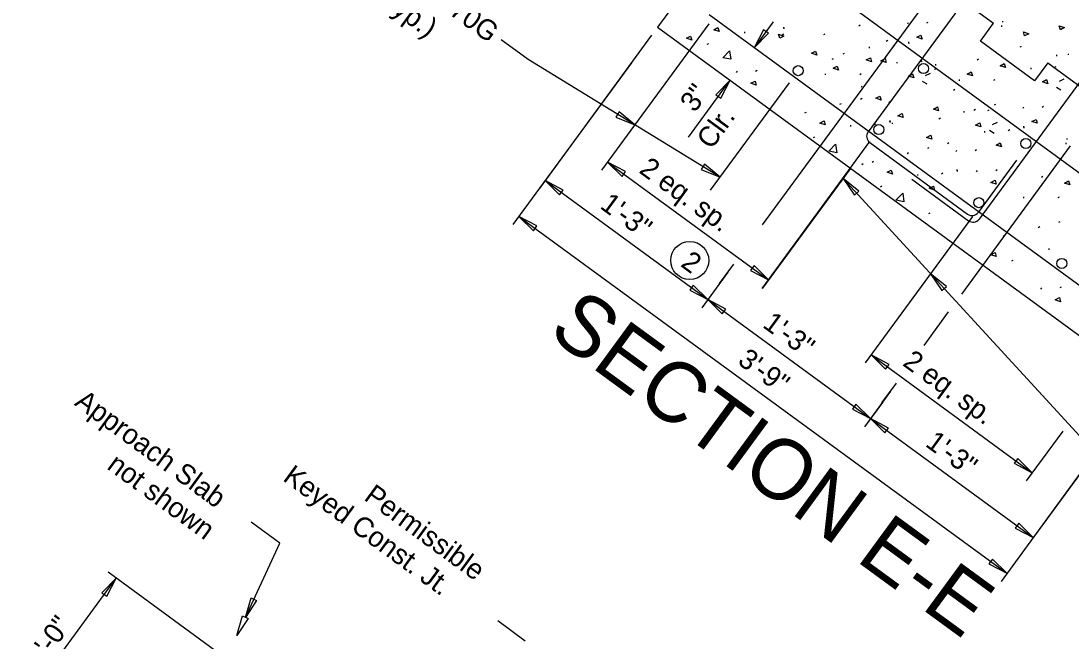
# Model space of a CAD drawing. Extents: x 1970654 to 1970899, y 796145 to 796378.
# Drawn here: x 1970798.44 to 1970824.47, y 796220.79 to 796236.18 of the extents above; entities that cross this region are included whole.
import ezdxf

# ---------------------------------------------------------------- set-up
doc = ezdxf.new("R2010")
doc.units = 0
for name, color, linetype in [('BR_AUTO DIMENSION', 7, 'Continuous'), ('BR_CONCRETE', 7, 'Continuous'), ('BR_DETAILS', 7, 'Continuous'), ('BR_REBAR', 7, 'Continuous'), ('BR_TEXT', 7, 'Continuous')]:
    doc.layers.add(name, color=color, linetype=linetype)

msp = doc.modelspace()

# ---------------------------------------------------------------- linework, layer by layer
at = {"layer": 'BR_AUTO DIMENSION'}
for p, q in [((1970816.823, 796231.114), (1970820.99, 796236.805)), ((1970817.087, 796236.158), (1970816.614, 796235.513)), ((1970815.495, 796236.106), (1970812.833, 796232.471)), ((1970811.013, 796235.217), (1970810.343, 796235.707)), ((1970814.074, 796235.823), (1970811.284, 796232.012)), ((1970813.572, 796235.138), (1970810.634, 796231.125)), ((1970815.772, 796232.296), (1970811.013, 796235.217)), ((1970814.986, 796233.289), (1970816.024, 796234.706)), ((1970815.536, 796231.973), (1970817.491, 796234.645)), ((1970816.815, 796229.532), (1970819.488, 796233.183)), ((1970821.764, 796229.399), (1970824.457, 796233.077)), ((1970812.98, 796232.672), (1970816.974, 796229.749)), ((1970818.993, 796232.507), (1970816.826, 796229.547)), ((1970818.822, 796232.27), (1970826.545, 796223.839)), ((1970811.431, 796232.214), (1970815.466, 796229.26)), ((1970810.782, 796231.327), (1970822.884, 796222.466)), ((1970822.029, 796231.322), (1970819.367, 796227.687)), ((1970815.759, 796229.661), (1970816.109, 796230.139)), ((1970815.961, 796229.938), (1970815.318, 796229.059)), ((1970815.961, 796229.938), (1970815.318, 796229.059)), ((1970815.466, 796229.26), (1970819.5, 796226.307)), ((1970820.828, 796228.121), (1970821.437, 796228.953)), ((1970819.515, 796227.888), (1970823.512, 796224.962)), ((1970819.783, 796226.694), (1970820.143, 796227.186)), ((1970819.996, 796226.984), (1970819.352, 796226.105)), ((1970819.795, 796226.709), (1970819.352, 796226.105)), ((1970819.5, 796226.307), (1970823.534, 796223.353)), ((1970824.27, 796225.997), (1970823.364, 796224.76)), ((1970824.888, 796225.202), (1970823.386, 796223.151)), ((1970824.86, 796225.163), (1970822.737, 796222.264)), ((1970804.851, 796223.217), (1970804.14, 796223.738)), ((1970804.001, 796221.371), (1970804.851, 796223.217)), ((1970798.436, 796219.117), (1970800.799, 796222.345)), ((1970806.849, 796217.915), (1970800.598, 796222.492)), ((1970810.941, 796220.785), (1970810.259, 796221.285))]:
    msp.add_line(p, q, dxfattribs=at)
for points in [[(1970816.849, 796235.961), (1970816.614, 796235.513), (1970816.97, 796235.872)], [(1970815.789, 796234.258), (1970816.024, 796234.706), (1970815.668, 796234.347)], [(1970813.189, 796233.793), (1970813.655, 796233.595), (1970813.268, 796233.921)], [(1970813.428, 796232.437), (1970812.98, 796232.672), (1970813.339, 796232.316)], [(1970815.305, 796232.494), (1970815.771, 796232.296), (1970815.384, 796232.622)], [(1970819.215, 796231.952), (1970818.822, 796232.27), (1970819.104, 796231.85)], [(1970811.879, 796231.979), (1970811.431, 796232.214), (1970811.79, 796231.858)], [(1970811.229, 796231.092), (1970810.782, 796231.327), (1970811.141, 796230.971)], [(1970816.526, 796229.983), (1970816.974, 796229.749), (1970816.615, 796230.104)], [(1970821.383, 796229.585), (1970820.99, 796229.903), (1970821.272, 796229.484)], [(1970815.018, 796229.495), (1970815.466, 796229.26), (1970815.106, 796229.616)], [(1970815.913, 796229.025), (1970815.466, 796229.26), (1970815.825, 796228.904)], [(1970819.962, 796227.653), (1970819.515, 796227.888), (1970819.874, 796227.532)], [(1970819.052, 796226.541), (1970819.5, 796226.307), (1970819.141, 796226.662)], [(1970819.948, 796226.072), (1970819.5, 796226.307), (1970819.859, 796225.951)], [(1970823.064, 796225.197), (1970823.512, 796224.962), (1970823.153, 796225.318)], [(1970823.086, 796223.588), (1970823.534, 796223.353), (1970823.175, 796223.709)], [(1970822.437, 796222.7), (1970822.884, 796222.466), (1970822.525, 796222.821)], [(1970800.564, 796221.897), (1970800.799, 796222.345), (1970800.443, 796221.985)], [(1970804.278, 796221.794), (1970804.001, 796221.371), (1970804.142, 796221.856)], [(1970804.066, 796221.346), (1970803.789, 796220.924), (1970803.93, 796221.409)]]:
    msp.add_lwpolyline(points, close=True, dxfattribs=at)
msp.add_circle((1970815.018, 796230.231), 0.472, dxfattribs=at)
at = {"layer": 'BR_CONCRETE'}
for p, q in [((1970817.175, 796240.06), (1970814.222, 796236.025)), ((1970821.21, 796237.106), (1970822.554, 796236.121)), ((1970814.222, 796236.025), (1970826.325, 796227.164)), ((1970823.899, 796235.137), (1970825.244, 796234.152))]:
    msp.add_line(p, q, dxfattribs=at)
msp.add_lwpolyline([(1970823.899, 796235.137), (1970823.571, 796234.688), (1970822.226, 796235.673), (1970822.554, 796236.121)], dxfattribs=at)
at = {"layer": 'BR_DETAILS'}
for p, q in [((1970820.435, 796236.128), (1970820.416, 796236.095)), ((1970820.897, 796236.13), (1970820.933, 796236.151)), ((1970822.772, 796236.176), (1970822.77, 796236.146)), ((1970816.375, 796235.905), (1970816.373, 796235.875)), ((1970817.345, 796236.025), (1970817.344, 796235.995)), ((1970817.353, 796236.008), (1970817.352, 796235.978)), ((1970819.208, 796236.056), (1970819.243, 796236.077)), ((1970822.752, 796236.063), (1970822.751, 796236.033)), ((1970815.454, 796235.599), (1970815.49, 796235.619)), ((1970816.851, 796235.831), (1970816.832, 796235.798)), ((1970817.313, 796235.833), (1970817.349, 796235.854)), ((1970818.34, 796235.84), (1970818.375, 796235.861)), ((1970819.893, 796235.678), (1970819.928, 796235.698)), ((1970820.441, 796235.655), (1970820.439, 796235.625)), ((1970820.449, 796235.637), (1970820.447, 796235.607)), ((1970818.825, 796235.361), (1970818.86, 796235.381)), ((1970819.47, 796235.534), (1970819.469, 796235.504)), ((1970820.06, 796235.551), (1970820.096, 796235.571)), ((1970823.214, 796235.533), (1970823.249, 796235.554)), ((1970824.413, 796235.333), (1970824.414, 796235.363)), ((1970818.55, 796235.228), (1970818.585, 796235.248)), ((1970820.155, 796235.156), (1970820.154, 796235.126)), ((1970820.745, 796235.173), (1970820.781, 796235.193)), ((1970821.114, 796235.103), (1970821.113, 796235.073)), ((1970822.146, 796235.216), (1970822.181, 796235.237)), ((1970824.124, 796235.305), (1970824.125, 796235.335)), ((1970816.191, 796234.93), (1970816.172, 796234.897)), ((1970816.653, 796234.932), (1970816.689, 796234.953)), ((1970818.376, 796234.868), (1970818.375, 796234.838)), ((1970819.235, 796234.85), (1970819.27, 796234.87)), ((1970820.866, 796234.826), (1970820.986, 796234.884)), ((1970821.095, 796234.99), (1970821.094, 796234.96)), ((1970823.476, 796235.011), (1970823.475, 796234.981)), ((1970824.066, 796235.028), (1970824.102, 796235.048)), ((1970820.903, 796234.605), (1970820.789, 796234.674)), ((1970821.697, 796234.723), (1970821.696, 796234.693)), ((1970822.556, 796234.705), (1970822.591, 796234.725)), ((1970824.187, 796234.681), (1970824.307, 796234.739)), ((1970819.286, 796234.559), (1970819.268, 796234.526)), ((1970821.556, 796234.46), (1970821.592, 796234.481)), ((1970824.224, 796234.46), (1970824.11, 796234.529)), ((1970818.744, 796234.109), (1970818.78, 796234.13)), ((1970819.255, 796234.236), (1970819.291, 796234.257)), ((1970819.971, 796234.181), (1970819.953, 796234.148)), ((1970822.576, 796234.091), (1970822.612, 796234.112)), ((1970823.755, 796234.038), (1970823.79, 796234.059)), ((1970817.876, 796233.893), (1970817.912, 796233.913)), ((1970821.819, 796233.938), (1970821.817, 796233.908)), ((1970822.065, 796233.964), (1970822.101, 796233.985)), ((1970822.409, 796233.955), (1970822.444, 796233.975)), ((1970823.292, 796234.036), (1970823.274, 796234.003)), ((1970819.007, 796233.587), (1970819.005, 796233.557)), ((1970819.597, 796233.604), (1970819.632, 796233.624)), ((1970819.977, 796233.707), (1970819.976, 796233.677)), ((1970819.985, 796233.69), (1970819.984, 796233.66)), ((1970820.04, 796233.65), (1970820.038, 796233.62)), ((1970821.197, 796233.748), (1970821.233, 796233.769)), ((1970822.53, 796233.608), (1970822.65, 796233.666)), ((1970823.298, 796233.563), (1970823.297, 796233.533)), ((1970823.306, 796233.545), (1970823.305, 796233.515)), ((1970818.086, 796233.281), (1970818.122, 796233.301)), ((1970822.328, 796233.442), (1970822.326, 796233.412)), ((1970822.566, 796233.387), (1970822.452, 796233.456)), ((1970822.918, 796233.459), (1970822.953, 796233.479)), ((1970824.367, 796233.263), (1970824.365, 796233.233)), ((1970820.919, 796233.018), (1970820.954, 796233.039)), ((1970821.407, 796233.136), (1970821.442, 796233.156)), ((1970824.347, 796233.15), (1970824.346, 796233.12)), ((1970820.408, 796232.891), (1970820.443, 796232.912)), ((1970821.635, 796232.963), (1970821.616, 796232.93)), ((1970822.097, 796232.965), (1970822.133, 796232.986)), ((1970819.285, 796232.614), (1970819.321, 796232.635)), ((1970819.54, 796232.675), (1970819.575, 796232.695)), ((1970821.641, 796232.49), (1970821.639, 796232.46)), ((1970822.606, 796232.469), (1970822.642, 796232.49)), ((1970820.67, 796232.369), (1970820.669, 796232.339)), ((1970821.26, 796232.386), (1970821.296, 796232.406)), ((1970821.648, 796232.472), (1970821.647, 796232.442)), ((1970822.144, 796232.467), (1970822.125, 796232.434)), ((1970823.741, 796232.303), (1970823.776, 796232.324)), ((1970819.749, 796232.063), (1970819.785, 796232.083)), ((1970823.292, 796231.81), (1970823.291, 796231.78)), ((1970824.151, 796231.792), (1970824.186, 796231.812)), ((1970820.949, 796231.396), (1970820.984, 796231.417)), ((1970824.171, 796231.179), (1970824.207, 796231.199)), ((1970823.66, 796231.051), (1970823.696, 796231.072)), ((1970822.792, 796230.835), (1970822.828, 796230.856)), ((1970823.923, 796230.529), (1970823.921, 796230.499)), ((1970823.002, 796230.223), (1970823.037, 796230.243)), ((1970823.739, 796229.554), (1970823.72, 796229.521)), ((1970824.201, 796229.557), (1970824.237, 796229.577))]:
    msp.add_line(p, q, dxfattribs=at)
for points in [[(1970815.615, 796235.958), (1970815.717, 796236.012), (1970815.747, 796235.913), (1970815.615, 796235.958)], [(1970823.424, 796235.86), (1970823.322, 796235.806), (1970823.292, 796235.905), (1970823.424, 796235.86)], [(1970824.315, 796236.012), (1970824.213, 796235.958), (1970824.183, 796236.057), (1970824.315, 796236.012)], [(1970814.94, 796235.748), (1970815.041, 796235.802), (1970815.072, 796235.703), (1970814.94, 796235.748)], [(1970817.351, 796235.802), (1970817.249, 796235.748), (1970817.219, 796235.848), (1970817.351, 796235.802)], [(1970820.646, 796235.773), (1970820.748, 796235.827), (1970820.778, 796235.728), (1970820.646, 796235.773)], [(1970815.837, 796235.265), (1970816.005, 796235.437), (1970816.034, 796235.225), (1970815.841, 796235.264)], [(1970818.035, 796235.377), (1970818.137, 796235.431), (1970818.167, 796235.332), (1970818.035, 796235.377)], [(1970819.396, 796235.209), (1970819.497, 796235.263), (1970819.528, 796235.164), (1970819.396, 796235.209)], [(1970819.759, 796235.188), (1970819.861, 796235.243), (1970819.891, 796235.143), (1970819.759, 796235.188)], [(1970822.717, 796235.064), (1970822.818, 796235.119), (1970822.849, 796235.019), (1970822.717, 796235.064)], [(1970818.573, 796235.003), (1970818.675, 796235.058), (1970818.706, 796234.958), (1970818.573, 796235.003)], [(1970820.444, 796234.81), (1970820.546, 796234.865), (1970820.576, 796234.765), (1970820.444, 796234.81)], [(1970821.894, 796234.859), (1970821.996, 796234.913), (1970822.026, 796234.813), (1970821.894, 796234.859)], [(1970816.535, 796234.63), (1970816.637, 796234.684), (1970816.667, 796234.585), (1970816.535, 796234.63)], [(1970823.765, 796234.665), (1970823.867, 796234.72), (1970823.897, 796234.62), (1970823.765, 796234.665)], [(1970819.63, 796234.259), (1970819.732, 796234.314), (1970819.762, 796234.214), (1970819.63, 796234.259)], [(1970821.059, 796233.991), (1970821.161, 796234.045), (1970821.191, 796233.946), (1970821.059, 796233.991)], [(1970820.182, 796233.826), (1970820.284, 796233.88), (1970820.314, 796233.78), (1970820.182, 796233.826)], [(1970818.247, 796233.64), (1970818.349, 796233.695), (1970818.379, 796233.595), (1970818.247, 796233.64)], [(1970822.107, 796233.592), (1970822.209, 796233.647), (1970822.24, 796233.547), (1970822.107, 796233.592)], [(1970823.503, 796233.681), (1970823.605, 796233.735), (1970823.635, 796233.636), (1970823.503, 796233.681)], [(1970820.892, 796233.285), (1970820.994, 796233.339), (1970821.024, 796233.24), (1970820.892, 796233.285)], [(1970818.469, 796232.947), (1970818.636, 796233.119), (1970818.666, 796232.907), (1970818.473, 796232.946)], [(1970822.616, 796233.096), (1970822.718, 796233.151), (1970822.748, 796233.051), (1970822.616, 796233.096)], [(1970819.91, 796232.422), (1970820.012, 796232.477), (1970820.043, 796232.377), (1970819.91, 796232.422)], [(1970822.488, 796232.167), (1970822.59, 796232.222), (1970822.62, 796232.122), (1970822.488, 796232.167)], [(1970820.959, 796232.023), (1970821.061, 796232.078), (1970821.091, 796231.978), (1970820.959, 796232.023)], [(1970824.312, 796232.151), (1970824.413, 796232.206), (1970824.444, 796232.106), (1970824.312, 796232.151)], [(1970820.133, 796231.729), (1970820.3, 796231.901), (1970820.329, 796231.689), (1970820.137, 796231.728)], [(1970822.487, 796230.372), (1970822.589, 796230.427), (1970822.619, 796230.327), (1970822.487, 796230.372)], [(1970824.083, 796229.254), (1970824.185, 796229.309), (1970824.215, 796229.209), (1970824.083, 796229.254)]]:
    msp.add_lwpolyline(points, dxfattribs=at)
at = {"layer": 'BR_REBAR'}
for p, q in [((1970823.624, 796239.134), (1970819.441, 796233.421)), ((1970827.556, 796230.291), (1970816.923, 796238.075)), ((1970826.448, 796237.067), (1970822.194, 796231.256)), ((1970826.226, 796228.475), (1970815.502, 796236.327)), ((1970819.482, 796233.159), (1970821.909, 796231.382)), ((1970823.121, 796232.72), (1970822.171, 796231.423)), ((1970820.526, 796232.25), (1970821.934, 796231.219))]:
    msp.add_line(p, q, dxfattribs=at)
for centre in [(1970820.814, 796234.994), (1970817.71, 796234.943), (1970819.707, 796233.481), (1970823.355, 796233.134), (1970822.186, 796231.666), (1970824.246, 796230.158)]:
    msp.add_circle(centre, 0.125, dxfattribs=at)
for centre, radius, start, end in [((1970819.593, 796233.311), 0.188, 143.7906, 233.7906), ((1970822.02, 796231.534), 0.187, 233.7906, 323.7906), ((1970822.045, 796231.37), 0.187, 233.7906, 323.7906)]:
    msp.add_arc(centre, radius, start, end, dxfattribs=at)

# ---------------------------------------------------------------- texts
at = {"layer": 'BR_AUTO DIMENSION'}
for s, rotation, p in [('3"', 53.7906, (1970815.144, 796233.883)), ('2 eq. sp.', 323.7906, (1970813.737, 796232.428)), ('1\'-3"', 323.7906, (1970812.768, 796231.545)), ('1\'-3"', 323.7906, (1970816.802, 796228.592)), ('3\'-9"', 323.7906, (1970816.18, 796227.684)), ('2 eq. sp.', 323.7906, (1970820.273, 796227.643)), ('1\'-3"', 323.7906, (1970820.836, 796225.638)), ('1\'-0"', 53.7906, (1970798.917, 796220.1))]:
    msp.add_text(s, height=0.5, rotation=rotation, dxfattribs=at).set_placement(p)
at = {"layer": 'BR_TEXT'}
for s, height, rotation, p in [('2-A1970G', 0.4999, 323.7906, (1970807.586, 796237.416)), ('(Typ.)', 0.4999, 323.7906, (1970807.113, 796236.769)), ('Clr.', 0.5, 53.7906, (1970815.556, 796232.965)), ('2', 0.5, 323.7906, (1970814.769, 796230.103)), ('SECTION E-E', 1.5, 323.7906, (1970811.465, 796228.391)), ('Approach Slab', 0.49995, 323.7906, (1970799.738, 796226.655)), ('not shown', 0.4999, 323.7906, (1970800.541, 796225.076)), ('Keyed Const. Jt.', 0.49995, 323.7906, (1970804.905, 796224.785)), ('Permissible', 0.49995, 323.7906, (1970806.915, 796224.305))]:
    msp.add_text(s, height=height, rotation=rotation, dxfattribs=at).set_placement(p)

doc.saveas('drawing.dxf')
